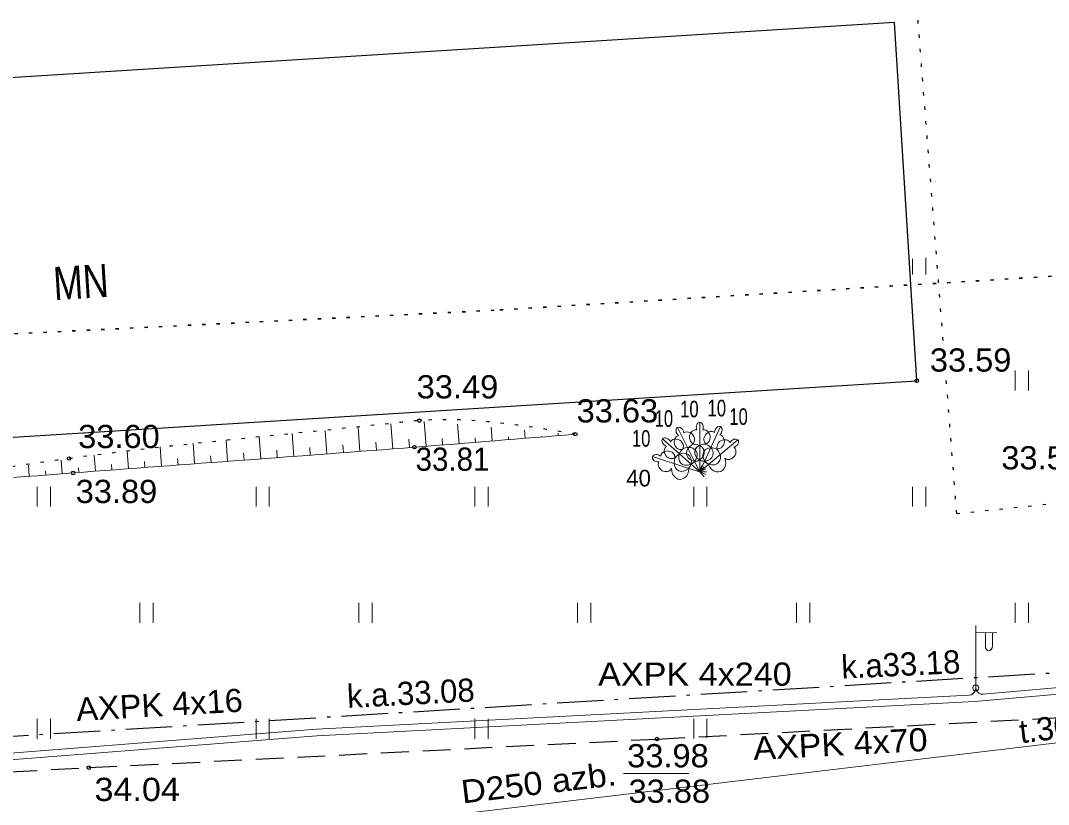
# Model space of a CAD drawing. Extents: x 380758 to 381729, y 283236 to 283533.
# Drawn here: x 381117.48 to 381148.48, y 283342.48 to 283366.12 of the extents above; entities that cross this region are included whole.
import ezdxf
from ezdxf.enums import TextEntityAlignment as Align

# ---------------------------------------------------------------- set-up
doc = ezdxf.new("R2010")
doc.units = 0
doc.header["$LTSCALE"] = 0.28
for name, pattern in [('DOT_DASHED', [7.7, 5, -1.2, 0.3, -1.2]), ('DOTTED', [1.5, 0.3, -1.2]), ('MEDIUM_DASHED', [4.5, 3, -1.5])]:
    doc.linetypes.add(name, pattern=pattern)
for name, color, linetype, lineweight in [('1', 7, 'Continuous', 13), ('11', 7, 'Continuous', 13), ('23', 7, 'Continuous', 13), ('25', 7, 'DOTTED', 35), ('29', 7, 'DOT_DASHED', 25), ('31', 7, 'Continuous', 13), ('37', 7, 'MEDIUM_DASHED', 13), ('4', 7, 'Continuous', 13), ('40', 7, 'Continuous', 25), ('44', 7, 'Continuous', 13), ('45', 7, 'Continuous', 13), ('58', 7, 'Continuous', 25), ('7', 7, 'Continuous', 13)]:
    doc.layers.add(name, color=color, linetype=linetype, lineweight=lineweight)

msp = doc.modelspace()

# ---------------------------------------------------------------- linework, layer by layer
at = {"layer": '1'}
for p, q in [((381137.292, 283353.851), (381137.806, 283352.819)), ((381137.961, 283354.008), (381137.961, 283352.855)), ((381138.584, 283353.873), (381138.105, 283352.824)), ((381137.476, 283353.683), (381137.475, 283353.683)), ((381138.051, 283353.776), (381138.05, 283353.777)), ((381138.569, 283353.624), (381138.568, 283353.625)), ((381136.84, 283353.505), (381137.702, 283352.739)), ((381137.073, 283353.417), (381137.072, 283353.417)), ((381139.111, 283353.471), (381138.227, 283352.731)), ((381138.99, 283353.253), (381138.99, 283353.254)), ((381136.533, 283352.968), (381137.631, 283352.614)), ((381136.782, 283352.982), (381136.781, 283352.981)), ((381137.631, 283352.614), (381137.961, 283352.508)), ((381137.702, 283352.739), (381137.961, 283352.508)), ((381137.806, 283352.819), (381137.961, 283352.508)), ((381137.961, 283352.855), (381137.961, 283352.508)), ((381138.105, 283352.824), (381137.961, 283352.508)), ((381138.227, 283352.731), (381137.961, 283352.508)), ((381137.961, 283352.508), (381138.022, 283352.698)), ((381137.961, 283352.508), (381138.094, 283352.657)), ((381137.961, 283352.508), (381138.14, 283352.597)), ((381137.961, 283352.508), (381138.161, 283352.508)), ((381137.961, 283352.508), (381138.143, 283352.425)), ((381137.961, 283352.508), (381138.089, 283352.355))]:
    msp.add_line(p, q, dxfattribs=at)
for centre, major_axis, ratio, start_param, end_param in [((381137.3594, 283353.7166), (0.0669, -0.1342), 0.707107, 3.1453698, 5.2874846), ((381137.3586, 283353.7162), (0.0669, -0.1342), 0.707107, 0.9957007, 3.1378155), ((381137.9614, 283353.8581), (0, -0.1499), 0.707107, 3.1453698, 5.2874846), ((381137.9606, 283353.8581), (0, -0.1499), 0.707107, 0.9957007, 3.1378155), ((381138.522, 283353.736), (-0.0623, -0.1364), 0.707107, 3.1453698, 5.2874846), ((381138.5213, 283353.7363), (-0.0623, -0.1364), 0.707107, 0.9957007, 3.1378155), ((381136.952, 283353.405), (0.112, -0.0997), 0.707107, 0.9957007, 3.1378155), ((381137.2579, 283353.3052), (0.1844, -0.1122), 0.861323, 0, 3.1415927), ((381137.3756, 283353.3953), (0.06, -0.2074), 0.861323, 3.1415927, 6.2831853), ((381137.6053, 283353.5097), (0.1294, -0.1728), 0.861323, 0, 3.1415927), ((381137.8327, 283353.5632), (-0.0387, -0.2124), 0.861323, 3.1415927, 6.2831853), ((381138.0893, 283353.5632), (0.0387, -0.2124), 0.861323, 6.2831853, 9.424778), ((381138.2825, 283353.5212), (-0.1234, -0.1771), 0.861323, 3.1415927, 6.2831853), ((381138.5159, 283353.4147), (-0.053, -0.2093), 0.861323, 6.2831853, 9.424778), ((381136.9525, 283353.4056), (0.112, -0.0997), 0.707107, 3.1453698, 5.2874846), ((381137.0873, 283353.1135), (0.133, -0.1701), 0.861323, 3.1415927, 6.2831853), ((381137.5775, 283352.969), (-0.275, -0.166), 0.814445, 1.5311707, 4.712389), ((381137.8714, 283353.1009), (0.3068, 0.0951), 0.814445, 1.5707963, 4.7520146), ((381137.7768, 283353.0786), (-0.317, -0.0517), 0.814445, 1.5311707, 4.712389), ((381138.1257, 283353.0846), (0.3186, -0.0409), 0.814445, 1.5707963, 4.7520146), ((381138.0506, 283353.1009), (-0.3068, 0.0951), 0.814445, 1.5311707, 4.712389), ((381138.3581, 283352.9573), (0.2699, -0.1742), 0.814445, 1.5707963, 4.7520146), ((381138.2887, 283353.0102), (-0.2396, 0.2139), 0.814445, 1.5311707, 4.712389), ((381138.6877, 283353.2838), (-0.1877, -0.1067), 0.861323, 3.1415927, 6.2831853), ((381138.8524, 283353.0871), (-0.138, -0.1661), 0.861323, 6.2831853, 9.424778), ((381138.9964, 283353.3744), (-0.115, -0.0963), 0.707107, 3.1453698, 5.2874846), ((381138.9959, 283353.375), (-0.115, -0.0963), 0.707107, 0.9957007, 3.1378155), ((381136.676, 283352.9222), (0.1427, -0.046), 0.707107, 3.1453698, 5.2874846), ((381136.6758, 283352.9214), (0.1427, -0.046), 0.707107, 0.9957007, 3.1378155), ((381136.9959, 283352.9535), (0.2141, -0.0282), 0.861323, 6.2831853, 9.424778), ((381137.4585, 283352.8352), (0.1329, 0.2925), 0.814445, 1.5707963, 4.7520146), ((381137.4241, 283352.775), (-0.1846, -0.2629), 0.814445, 1.5311707, 4.712389), ((381137.6165, 283352.9988), (0.2322, 0.2219), 0.814445, 1.5707963, 4.7520146), ((381138.4731, 283352.82), (-0.124, 0.2963), 0.814445, 1.5311707, 4.712389), ((381136.9173, 283352.7093), (0.1903, -0.102), 0.861323, 3.1415927, 6.2831853), ((381137.3692, 283352.6045), (0.0035, 0.3212), 0.814445, 1.5707963, 4.7520146)]:
    msp.add_ellipse(centre, major_axis=major_axis, ratio=ratio, start_param=start_param, end_param=end_param, dxfattribs=at)
at = {"layer": '11'}
msp.add_line((381114.289, 283340.241), (381153.016, 283344.852), dxfattribs=at)
at = {"layer": '23'}
for p, q in [((381144.377, 283358.461), (381144.377, 283358.931)), ((381144.777, 283358.461), (381144.777, 283358.966)), ((381147.477, 283354.961), (381147.477, 283355.561)), ((381147.877, 283354.961), (381147.877, 283355.561)), ((381117.977, 283351.461), (381117.977, 283352.061)), ((381118.377, 283351.461), (381118.377, 283352.061)), ((381124.577, 283351.461), (381124.577, 283352.061)), ((381124.977, 283351.461), (381124.977, 283352.061)), ((381131.177, 283351.461), (381131.177, 283352.061)), ((381131.577, 283351.461), (381131.577, 283352.061)), ((381137.777, 283351.461), (381137.777, 283352.061)), ((381138.177, 283351.461), (381138.177, 283352.061)), ((381144.377, 283351.461), (381144.377, 283352.061)), ((381144.777, 283351.461), (381144.777, 283352.061)), ((381121.077, 283347.961), (381121.077, 283348.561)), ((381121.477, 283347.961), (381121.477, 283348.561)), ((381127.677, 283347.961), (381127.677, 283348.561)), ((381128.077, 283347.961), (381128.077, 283348.561)), ((381134.277, 283347.961), (381134.277, 283348.561)), ((381134.677, 283347.961), (381134.677, 283348.561)), ((381140.877, 283347.961), (381140.877, 283348.561)), ((381141.277, 283347.961), (381141.277, 283348.561)), ((381147.477, 283347.961), (381147.477, 283348.561)), ((381147.877, 283347.961), (381147.877, 283348.561)), ((381117.977, 283344.461), (381117.977, 283345.061)), ((381118.377, 283344.461), (381118.377, 283345.061)), ((381124.577, 283344.461), (381124.577, 283345.061)), ((381124.977, 283344.461), (381124.977, 283345.061)), ((381131.177, 283344.461), (381131.177, 283345.061)), ((381131.577, 283344.461), (381131.577, 283345.061)), ((381137.777, 283344.474), (381137.777, 283345.061)), ((381138.177, 283344.494), (381138.177, 283345.061))]:
    msp.add_line(p, q, dxfattribs=at)
at = {"layer": '25'}
msp.add_lwpolyline([(381378.132, 283376.241), (381330.368, 283370.09), (381282.589, 283365.052), (381241.341, 283362.776), (381227.597, 283363.335), (381201.225, 283361.612), (381131.764, 283357.382), (381089.163, 283355.29), (381056.824, 283352.96), (381046.619, 283367.047), (381043.733, 283420.739)], dxfattribs=at)
at = {"layer": '29'}
msp.add_line((381234.784, 283351.686), (381044.752, 283340.119), dxfattribs=at)
at = {"layer": '29', "linetype": 'DOTTED'}
msp.add_lwpolyline([(381144.327, 283368.738), (381145.7, 283351.253), (381234.058, 283360.366)], dxfattribs=at)
at = {"layer": '31'}
for p, q in [((381127.71, 283353.124), (381127.654, 283353.857)), ((381128.707, 283353.201), (381128.647, 283353.958)), ((381129.704, 283353.281), (381129.644, 283354.032)), ((381130.701, 283353.362), (381130.654, 283353.944)), ((381131.698, 283353.442), (381131.664, 283353.856)), ((381124.719, 283352.899), (381124.669, 283353.575)), ((381125.716, 283352.973), (381125.664, 283353.668)), ((381126.713, 283353.048), (381126.659, 283353.761)), ((381130.202, 283353.322), (381130.187, 283353.516)), ((381131.199, 283353.402), (381131.188, 283353.54)), ((381132.196, 283353.483), (381132.189, 283353.564)), ((381132.694, 283353.523), (381132.675, 283353.768)), ((381133.193, 283353.563), (381133.191, 283353.589)), ((381133.691, 283353.603), (381133.685, 283353.68)), ((381121.727, 283352.68), (381121.683, 283353.268)), ((381122.724, 283352.753), (381122.678, 283353.377)), ((381123.721, 283352.826), (381123.674, 283353.479)), ((381126.215, 283353.01), (381126.197, 283353.248)), ((381127.212, 283353.085), (381127.194, 283353.32)), ((381128.209, 283353.162), (381128.19, 283353.404)), ((381129.206, 283353.241), (381129.186, 283353.491)), ((381119.732, 283352.53), (381119.695, 283353.014)), ((381120.729, 283352.605), (381120.689, 283353.147)), ((381122.225, 283352.717), (381122.211, 283352.912)), ((381123.223, 283352.79), (381123.208, 283352.996)), ((381124.22, 283352.863), (381124.204, 283353.077)), ((381125.217, 283352.936), (381125.2, 283353.168)), ((381117.738, 283352.375), (381117.712, 283352.71)), ((381118.735, 283352.453), (381118.703, 283352.864)), ((381119.234, 283352.491), (381119.223, 283352.634)), ((381120.231, 283352.568), (381120.218, 283352.732)), ((381121.228, 283352.643), (381121.215, 283352.824)), ((381118.237, 283352.414), (381118.228, 283352.531))]:
    msp.add_line(p, q, dxfattribs=at)
at = {"layer": '31', "linetype": 'DOTTED', "lineweight": 25}
msp.add_spline([(381134.207, 283353.645), (381129.502, 283354.054), (381128.81, 283353.986), (381118.938, 283352.911), (381113.252, 283352.025)], degree=3, dxfattribs=at)
at = {"layer": '31'}
msp.add_spline([(381113.252, 283352.025), (381119.062, 283352.478), (381129.352, 283353.253), (381134.207, 283353.645)], degree=3, dxfattribs=at)
at = {"layer": '37', "lineweight": 25}
msp.add_lwpolyline([(381057.591, 283339.033), (381075.94, 283340.852), (381097.005, 283342.39), (381119.536, 283343.592), (381136.671, 283344.454), (381156.115, 283345.485), (381163.151, 283345.848), (381179.391, 283346.671), (381179.402, 283346.957), (381180.543, 283347.053), (381180.574, 283346.748), (381189.023, 283347.214), (381204.943, 283348.182)], dxfattribs=at)
at = {"layer": '40'}
msp.add_line((381095.786, 283352.218), (381144.505, 283355.256), dxfattribs=at)
msp.add_lwpolyline([(381144.505, 283355.256), (381143.832, 283366.055), (381095.113, 283363.017)], dxfattribs=at)
at = {"layer": '44'}
for p, q in [((381146.284, 283345.994), (381146.284, 283347.877)), ((381146.284, 283347.661), (381146.919, 283347.656)), ((381146.574, 283347.659), (381146.574, 283347.265)), ((381146.784, 283347.657), (381146.784, 283347.265))]:
    msp.add_line(p, q, dxfattribs=at)
msp.add_circle((381146.284, 283345.994), 0.09, dxfattribs=at)
msp.add_ellipse((381146.679, 283347.2645), major_axis=(0, -0.1509), ratio=0.695971, start_param=4.712389, end_param=7.8539816, dxfattribs=at)
at = {"layer": '45'}
for points in [[(381146.506, 283345.805), (381153.939, 283346.463), (381170.975, 283347.178), (381182.961, 283347.909)], [(381113.831, 283343.77), (381126.397, 283344.751), (381146.082, 283345.773)], [(381146.265, 283345.922), (381146.284, 283345.994), (381146.295, 283345.954)]]:
    msp.add_lwpolyline(points, dxfattribs=at)
for centre, start, end in [((381146.0716, 283345.9727), 272.97306, 345.29926), ((381146.4881, 283346.0043), 194.70074, 275.05503)]:
    msp.add_arc(centre, 0.2, start, end, dxfattribs=at)
at = {"layer": '58', "lineweight": 13}
msp.add_line((381135.66, 283343.41), (381137.626, 283343.41), dxfattribs=at)
at = {"layer": '58'}
for centre in [(381144.505, 283355.2561), (381129.502, 283354.0541), (381134.207, 283353.6451), (381129.352, 283353.2531), (381118.938, 283352.9111), (381119.062, 283352.4781), (381136.671, 283344.4541), (381119.536, 283343.5921)]:
    msp.add_circle(centre, 0.0534, dxfattribs=at)
at = {"layer": '7'}
msp.add_lwpolyline([(381114.594, 283343.629), (381126.41, 283344.551), (381146.242, 283345.581), (381153.952, 283346.263), (381170.985, 283346.978), (381183.147, 283347.72)], dxfattribs=at)

# ---------------------------------------------------------------- texts
at = {"layer": '1', "width": 0.75}
for p in [(381137.368, 283354.154), (381138.195, 283354.182), (381136.598, 283353.868), (381138.851, 283353.925), (381135.914, 283353.269)]:
    msp.add_text('10', height=0.5, dxfattribs=at).set_placement(p)
at = {"layer": '1'}
msp.add_text('40', height=0.5, dxfattribs=at).set_placement((381135.743, 283352.071))
at = {"layer": '11'}
msp.add_text('t.30.08', height=0.7, rotation=6.79, dxfattribs=at).set_placement((381149.0621, 283344.4936), align=Align.CENTER)
at = {"layer": '11', "width": 1.1}
msp.add_text('D250 azb.', height=0.7, rotation=6.79, dxfattribs=at).set_placement((381133.1396, 283342.7878), align=Align.CENTER)
at = {"layer": '4', "width": 0.8}
msp.add_text('MN', height=1, rotation=3.568, dxfattribs=at).set_placement((381118.496, 283357.684))
at = {"layer": '45', "width": 1.05}
msp.add_text('AXPK 4x16', height=0.7, rotation=3.226, dxfattribs=at).set_placement((381119.176, 283344.998))
at = {"layer": '58'}
for s, width, p in [('33.59', 1.05, (381144.899, 283355.532)), ('33.49', 1.05, (381129.423, 283354.724)), ('33.63', 1.05, (381134.246, 283354)), ('33.60', 1.05, (381119.214, 283353.226)), ('33.81', 0.95, (381129.391, 283352.542)), ('33.58', 1.05, (381147.055, 283352.584)), ('33.89', 1.05, (381119.14, 283351.57)), ('33.98', 1.05, (381135.771, 283343.6)), ('34.04', 1.1, (381119.705, 283342.585)), ('33.88', 1.05, (381135.812, 283342.532))]:
    msp.add_text(s, height=0.7, dxfattribs=dict(at, width=width)).set_placement(p)
at = {"layer": '7'}
for s, rotation, p in [('k.a33.18', 2.642, (381142.245, 283346.275)), ('k.a.33.08', 2.973, (381127.34, 283345.39))]:
    msp.add_text(s, height=0.7, rotation=rotation, dxfattribs=at).set_placement(p)
at = {"layer": '7', "width": 1.1}
msp.add_text('AXPK 4x240', height=0.7, dxfattribs=at).set_placement((381134.894, 283346.061))
msp.add_text('AXPK 4x70', height=0.7, rotation=2.973, dxfattribs=at).set_placement((381142.2173, 283343.9592), align=Align.CENTER)

doc.saveas('drawing.dxf')
